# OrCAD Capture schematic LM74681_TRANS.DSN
size Custom; title: TPS54233 :2A, 28V INPUT, STEP DOWN SWIFT; rev: 1.0; note: SNOSDG3 – DEC 2024
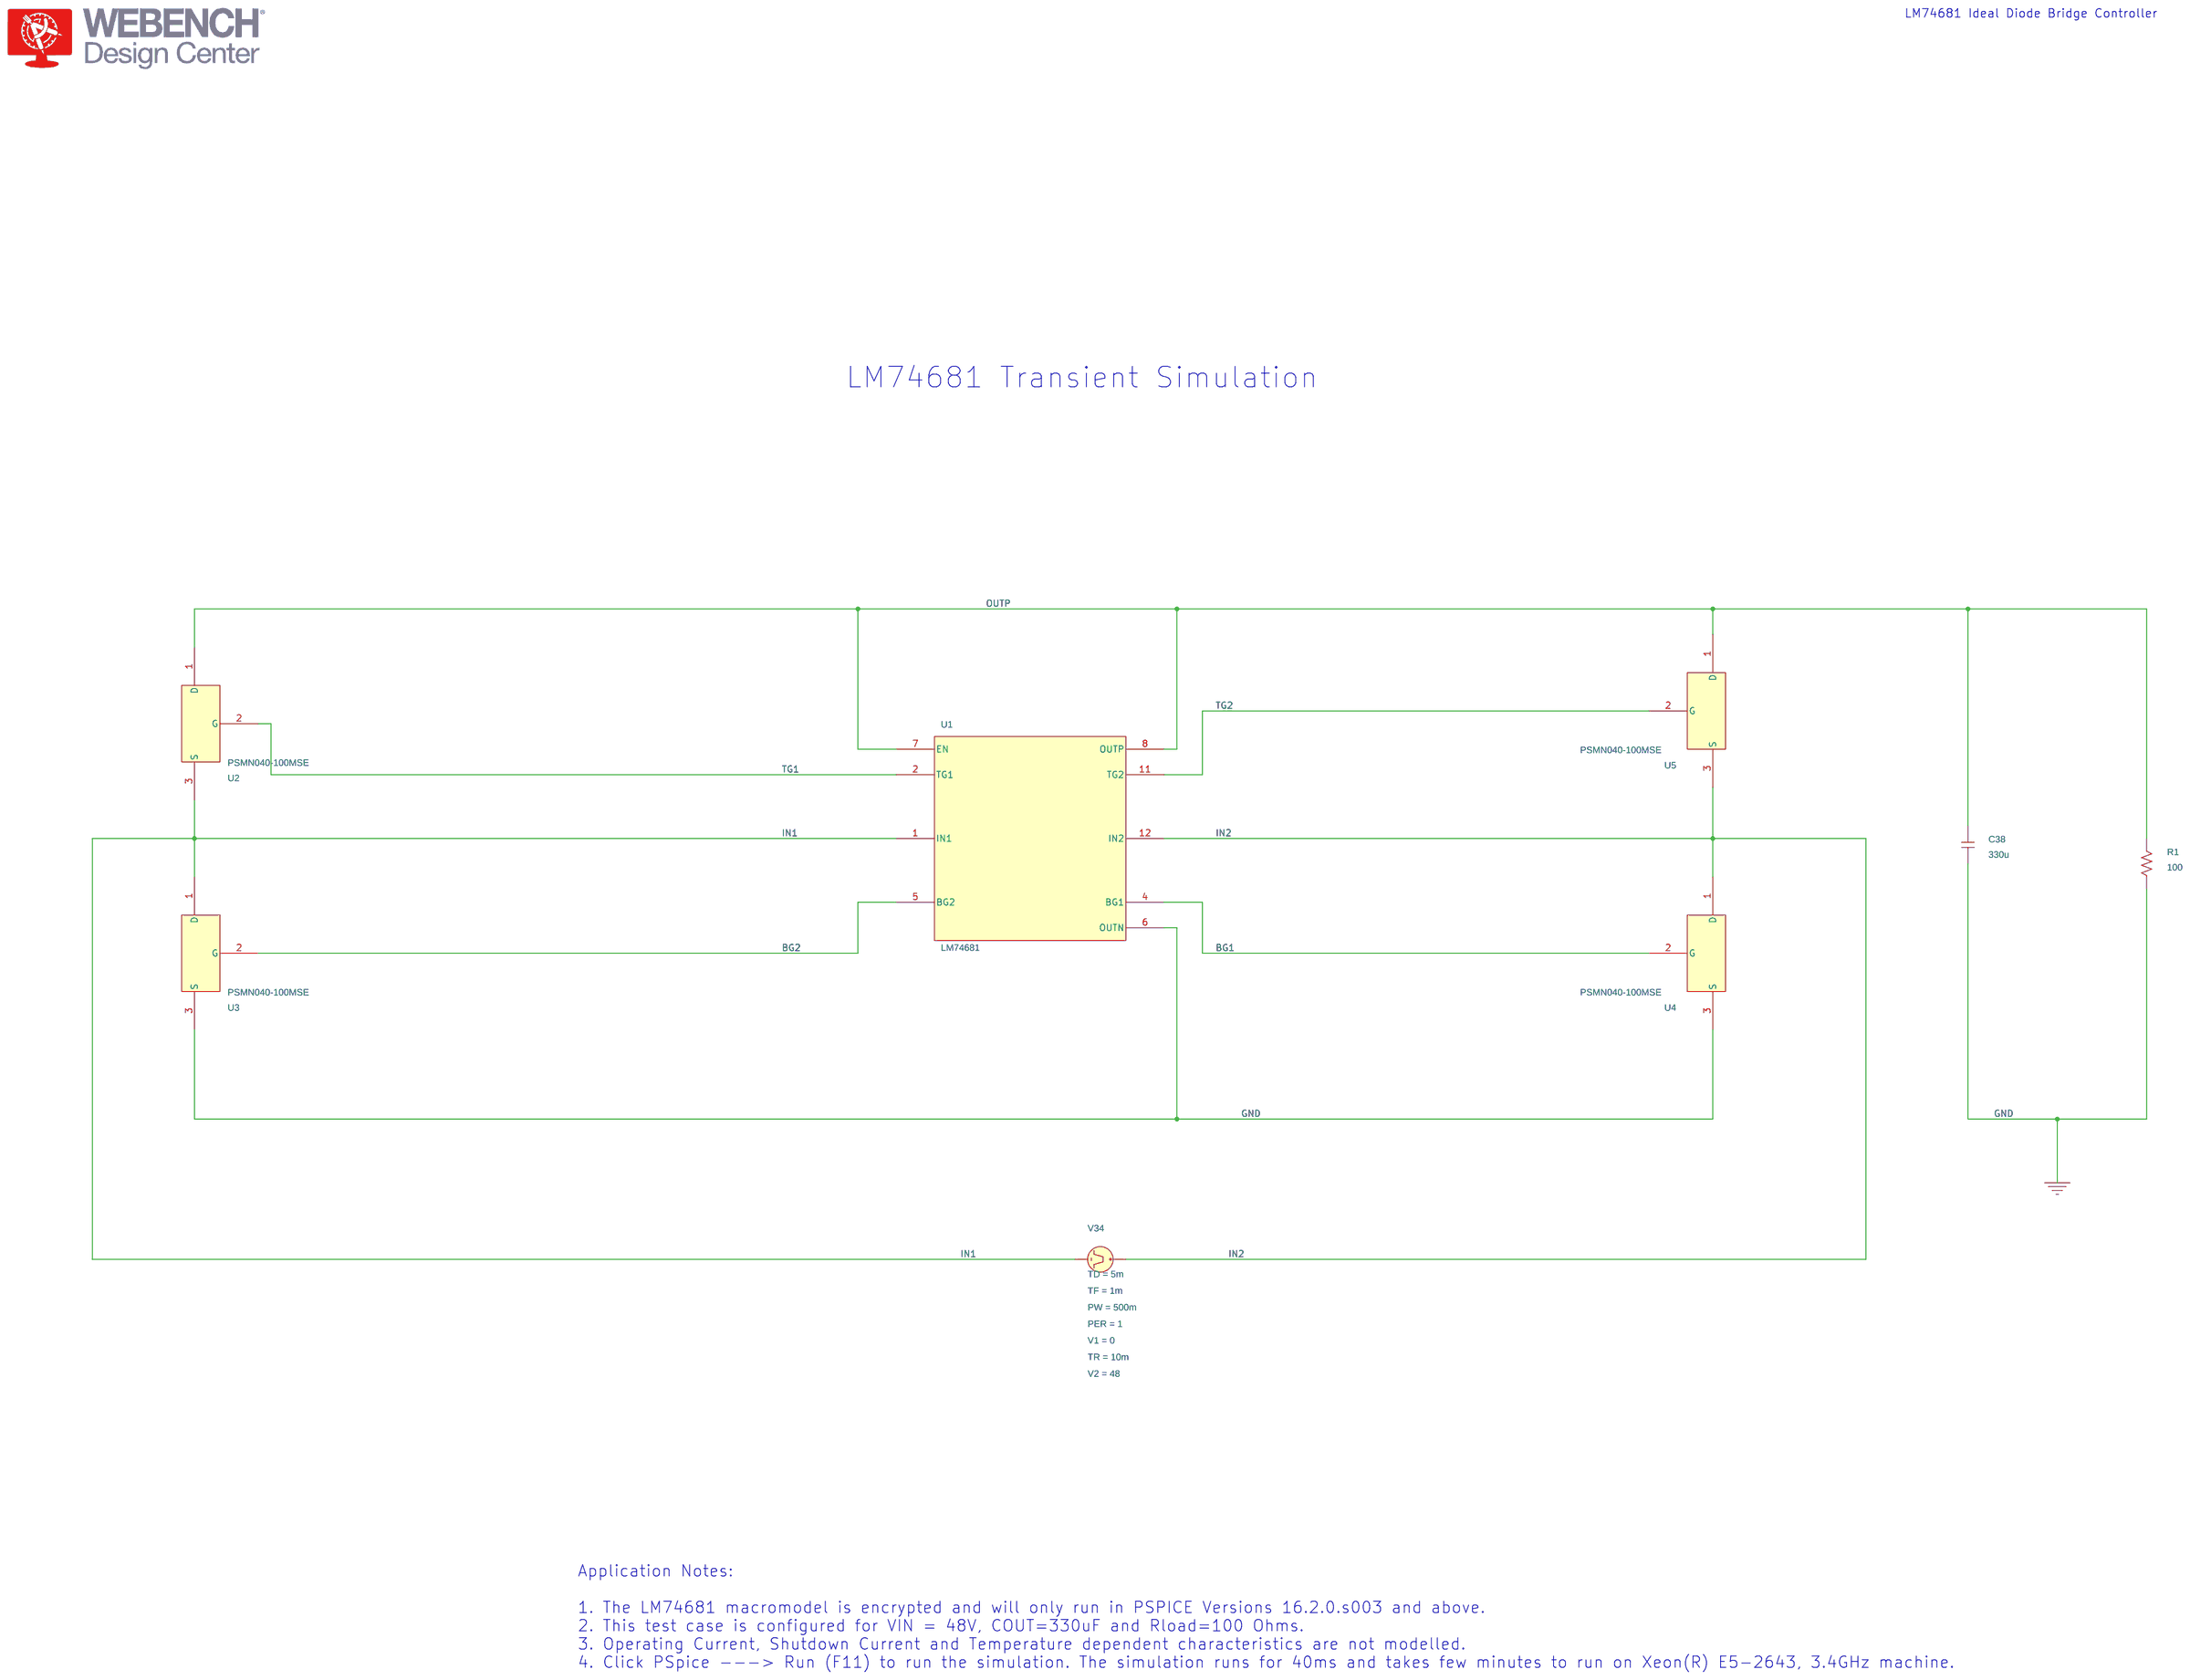
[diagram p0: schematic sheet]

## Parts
C38  330u  [cap196]
R1  100  [AXRC05]
U1  LM74681
U2  PSMN040-100MSE
U3  PSMN040-100MSE
U4  PSMN040-100MSE
U5  PSMN040-100MSE
V34  VPULSE

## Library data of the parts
C38 = C
R1 = R
U1 = LM74681
U2-U5 = PSMN040-100MSE
V34 = VPULSE: PER: 1; PW: 500m; TD: 5m; TF: 1m; TR: 10m; V1: 0; V2: 48

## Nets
0: C38.1 R1.1 U1.6(OUTN) U3.3(S) U4.3(S)
BG1: U1.4(BG1) U4.2(G)
BG2: U1.5(BG2) U3.2(G)
IN1: U1.1(IN1) U2.3(S) U3.1(D) V34.2(-)
IN2: U1.12(IN2) U4.1(D) U5.3(S) V34.1(+)
OUTP: C38.2 R1.2 U1.7(EN) U1.8(OUTP) U2.1(D) U5.1(D)
TG1: U1.2(TG1) U2.2(G)
TG2: U1.11(TG2) U5.2(G)

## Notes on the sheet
- LM74681 Ideal Diode Bridge Controller
- LM74681 Transient Simulation
- Application Notes:
  1. The LM74681 macromodel is encrypted and will only run in PSPICE Versions 16.2.0.s003 and above.
  2. This test case is configured for VIN = 48V, COUT=330uF and Rload=100 Ohms.
  3. Operating Current, Shutdown Current and Temperature dependent characteristics are not modelled.
  4. Click PSpice ---> Run (F11) to run the simulation. The simulation runs for 40ms and takes few minutes to run on Xeon(R) E5-2643, 3.4GHz machine.
